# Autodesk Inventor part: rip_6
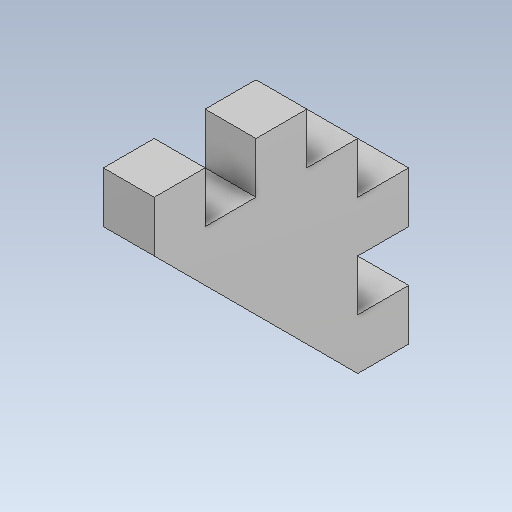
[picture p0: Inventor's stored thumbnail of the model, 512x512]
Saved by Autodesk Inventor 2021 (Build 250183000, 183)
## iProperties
Created: 2026-10
Part Number: rip_6
Material: Generic
Document SubType Name: Modeling
Designer: hp
Density: 1 g/cm^3
Appearance: Default
Author: hp
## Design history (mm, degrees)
feature "Body1"
body "Solid1"
